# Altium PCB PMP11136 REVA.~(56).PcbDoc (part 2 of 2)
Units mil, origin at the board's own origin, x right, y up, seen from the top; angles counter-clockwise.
Board outline 4320 x 3450 mil, 4 copper layers (Top Layer, Signal Layer 1, Signal Layer 2, Bottom Layer), stack 79.834 mil thick; 234 components, 94 nets, 538 pads, 218 vias.
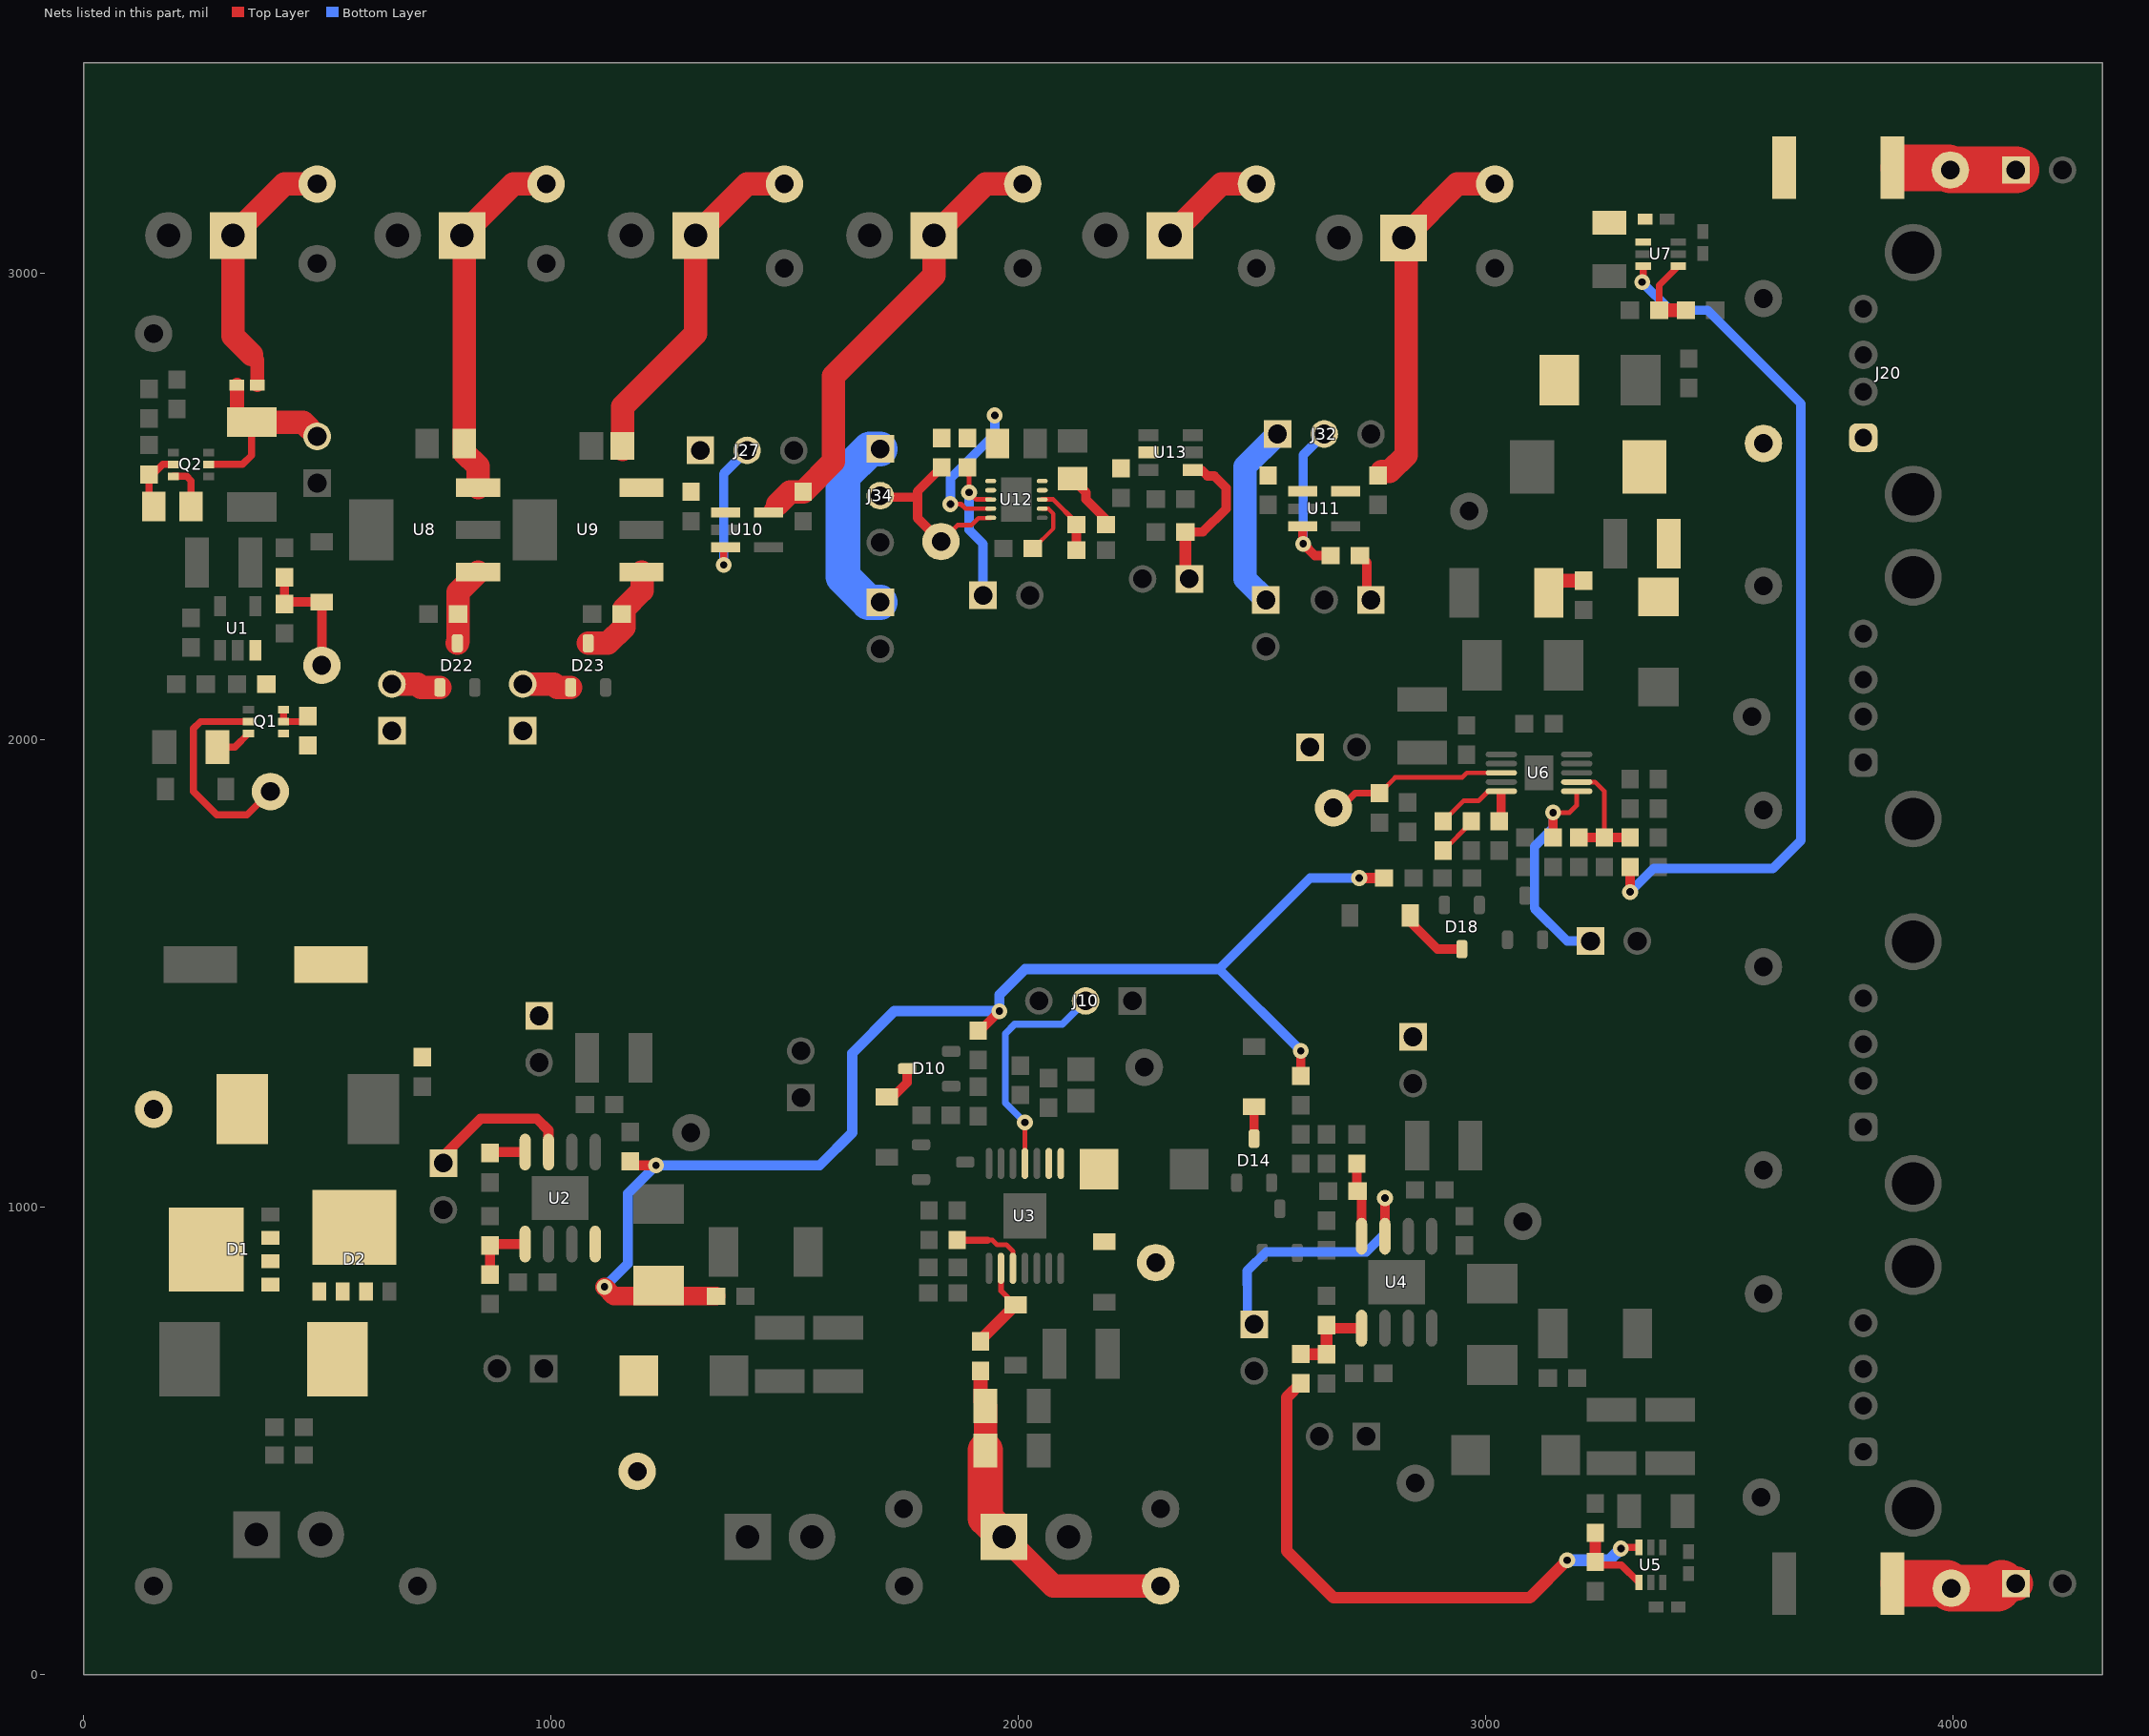
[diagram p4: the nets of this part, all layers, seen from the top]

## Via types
v1: diameter 34, hole 16, Top Layer to Bottom Layer, 193 vias
v2: diameter 19.68, hole 7.87, Top Layer to Bottom Layer, tented top, 12 vias
v3: diameter 18, hole 8, Top Layer to Bottom Layer, 5 vias
v4: diameter 15.75, hole 7.87, Top Layer to Bottom Layer, 4 vias
v5: diameter 19.68, hole 7.87, Top Layer to Bottom Layer, 4 vias

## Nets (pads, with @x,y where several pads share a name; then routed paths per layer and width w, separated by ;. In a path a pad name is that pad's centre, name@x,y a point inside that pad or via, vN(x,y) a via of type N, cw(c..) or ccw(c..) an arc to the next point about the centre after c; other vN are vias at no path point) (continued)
NetC39_2: C39.2 R45.2 | length 85.4
  Top Layer w30: R45.2@3135.55,2315 3162.05,2341.5 C39.2@3210,2341.5
NetC40_1: C40.1 TP25.1 U6.3 | length 390.4
  Top Layer w10: C40.1@2773.23,1886.5 2806.73,1920 2950,1920 2960,1930 U6.3@3033.98,1930
  Top Layer w15: TP25.1@2674.68,1855 2690,1855 2721.5,1886.5 C40.1@2773.23,1886.5
NetC41_1: C41.1 R39.2 | length 87.8
  Top Layer w10: R39.2@2909.68,1763.5 2969.68,1823.5 C41.1@2969.68,1826.5
NetC43_1: C43.1 C44.1 D17.2 L5.2
NetC45_1: C45.1 J20.1 R35.1 R37.2 TP42.1 U7.4
NetC47_1: C47.1 J23.1 TP30.1 U8.3 | length 779.2
  Top Layer w50: U8.3@844.17,2540.55 844.17,2585.83 815,2615 C47.1@815,2635 815,3075 J23.1@810,3080 920,3190 TP30.1@990,3190
NetC48_1: C48.1 D22.3 U8.1 | length 170.5
  Top Layer w50: D22.3@800,2207.24 800.39,2207.64 800.39,2210.39 801.5,2211.5 C48.1@801.5,2270 801.5,2316.77 U8.1@844.17,2359.45
NetC49_1: C49.1 C51.1 J24.1 J27.1 TP32.1 U9.3 U10.1 | length 758.2
  Top Layer w50: C49.1@1153.46,2622.17 C49.1@1153.46,2630 1153.46,2713.46 1310,2870 J24.1@1310,3080 1420,3190 TP32.1@1500,3190
NetC50_1: C50.1 D23.3 U9.1 | length 224.9
  Top Layer w50: D23.3@1080,2207.24 1122.24,2207.24 1156.46,2241.46 1156.46,2281.46 1195,2320 1195,2358.62 U9.1@1194.17,2359.45
NetC52_1: C52.1 J26.1 TP34.1 U10.5 | length 997.3
  Top Layer w20: U10.5@1466,2487.4 1466,2496 1475,2505
  Top Layer w30: 1475,2505 1485,2505
  Top Layer w50: 1485,2505 1511.5,2531.5 C52.1@1540,2531.5 1605,2596.5 1605,2779 1820,2994 J26.1@1820,3080 1930,3190 TP34.1@2010,3190
NetC53_1: C53.1 J28.1 J34.1 R49.2 R50.2 U12.1 U12.2 U12.4 | length 741.4
  Top Layer w10: v1(1855,2505) 1877.75,2505 1887.44,2495.32 U12.4@1941.18,2495.32
  Bottom Layer w20: v1(1855,2505) 1855,2560 1950,2655 v1(1950,2695)
  Bottom Layer w75: J28.1@1705,2295 1680,2295 1625,2350 1625,2565 1683.02,2623.02 J34.1@1705,2623.02
NetC54_1: C54.1 J31.1 TP37.1 U11.5 | length 787.7
  Top Layer w25: C54.1@2770,2566.5 C54.1@2778.5,2575
  Top Layer w50: C54.1@2778.5,2575 2795,2575 2830,2610 2830,3070 J31.1@2825,3075 2940,3190 TP37.1@3020,3190
NetC55_1: C55.1 J29.1 J32.1 U11.1 | length 402.6
  Bottom Layer w50: J29.1@2530,2300 2485,2345 2485,2585 J32.1@2555,2655
NetC56_1: C56.1 C59.1 J33.1 R51.2 TP36.1 U12.9 U12.10 U13.5 | length 358.9
  Top Layer w20: C56.1@2116.3,2560 2116.3,2558.7 2145,2530 2145,2515 2187.8,2472.2 R51.2@2187.8,2461.3
  Top Layer w50: J33.1@2325,3080 2435,3190 TP36.1@2510,3190
NetC57_1: C57.1 U12.7 | length 122
  Top Layer w9: C57.1@2031.5,2410 2032.48,2410 2075.6,2453.12 2075.6,2484.4 2064.68,2495.32 U12.7@2051.42,2495.32
NetD1_1: D1.1 D1.2 D1.3 D2.1 D2.2 D2.3 L1.2
NetD4_1: D4.1 J3.1 TP4.1 | length 567
  Top Layer w30: 360,2825 371.65,2813.35 D4.1@371.65,2760
  Top Layer w50: 360,2825 320,2865 J3.1@320,3080 430,3190 TP4.1@500,3190
NetD4_2: D4.2 J2.2 Q2.5 R1.2 | length 416.5
  Top Layer w15: Q2.5@267.4,2590 340,2590 360,2610 R1.2@360,2680.24
  Top Layer w20: 328.35,2711.89 R1.2@360,2680.24
  Top Layer w30: 328.35,2711.89 D4.2@328.35,2760
  Top Layer w50: R1.2@360,2680.24 360.24,2680 470,2680 J2.2@500,2650
NetD5_1: D5.1 R3.1 R7.1 TP7.1 | length 274.2
  Top Layer w20: R7.1@430,2348.5 R3.1@430,2291.5 434.04,2295.53 D5.1@510,2295.53 TP7.1@510,2160
NetD7_2: D7.2 L3.2 TP11.1 U3.1 U3.2
NetD8_2: D8.2 R11.2 U3.9 | length 200.8
  Top Layer w12: U3.9@1963.31,869.7 1963.31,821.69 1993.62,791.38 D8.2@1994.49,791.38
  Top Layer w25: R11.2@1919.49,713.41 1919.49,716.38 D8.2@1994.49,791.38
NetD10_3: D10.3 D12.1 | length 85.3
  Top Layer w20: D12.1@1719.49,1236.38 1731.46,1236.38 1762.24,1267.17 D10.3@1762.24,1296.91
NetD14_3: D14.3 D15.1 | length 68.3
  Top Layer w20: D14.3@2505,1147.24 D15.1@2505,1215.53
NetD18_3: D18.3 D20.1 | length 148.7
  Top Layer w20: D20.1@2839.15,1625 2839.15,1610.85 2897.24,1552.76 D18.3@2949.68,1552.76
NetD22_1: D22.1 J22.2 | length 105.6
  Top Layer w50: J22.2@660,2120 715,2120 722.24,2112.76 D22.1@762.6,2112.76
NetD23_1: D23.1 J25.2 | length 105.6
  Top Layer w50: J25.2@940,2120 1006.61,2120 1013.86,2112.76 D23.1@1042.6,2112.76
NetJ5_1: J5.1 U2.3 | length 330.1
  Top Layer w22: J5.1@770,1095 770,1110 850,1190 970,1190 995,1165 U2.3@995,1118.43
NetJ7_1: J7.1 R11.1 R17.2 R18.2 TP14.1 | length 754.8
  Top Layer w30: R11.1@1919.49,650.41 1919.49,585.51 R18.2@1930,575
  Top Layer w50: R17.2@1930,480 R18.2@1930,575 ; J7.1@1970,295 2075,190 TP14.1@2305,190
  Top Layer w75: R17.2@1930,480 1930,335 J7.1@1970,295
NetJ10_2: J10.2 U3.4 | length 495.9
  Top Layer w10: U3.4@2014.49,1094.11 v1(2014.49,1181.91)
  Bottom Layer w15: v1(2014.49,1181.91) 1972.63,1223.77 1972.63,1371.73 1992.81,1391.91 2094.49,1391.91 J10.2@2144.49,1441.91
NetJ12_1: J12.1 R22.2 TP17.1 | length 272.1
  Top Layer w50: R22.2@3871.14,195 R22.2@3895,195
  Top Layer w75: 4105,195 J12.1@4135,195
  Top Layer w100: R22.2@3895,195 3986.97,195 TP17.1@3996.97,185 4095,185 4105,195
NetJ13_1: J13.1 U4.3 | length 605.4
  Top Layer w20: U4.3@2785,938.43 v1(2785,1020)
  Bottom Layer w20: J13.1@2505,750 2490.68,764.32 2490.68,834.45 2490.13,835 2490.13,864.45 2530.68,905 2745,905 2785,945 v1(2785,1020)
NetJ18_1: J18.1 R36.2 U6.6 | length 511.3
  Top Layer w10: v1(3144.68,1845) 3180,1845 3195,1860 3195,1875 3195.39,1875.39 U6.6@3195.39,1890.63
  Top Layer w20: R36.2@3144.68,1791.5 v1(3144.68,1845)
  Bottom Layer w20: v1(3144.68,1845) 3144.68,1811.99 3105,1772.3 3105,1640 3175,1570 J18.1@3225,1570
NetJ19_1: J19.1 R35.2 TP23.1 | length 265.9
  Top Layer w50: R35.2@3871.14,3225 R35.2@3895,3225
  Top Layer w100: R35.2@3895,3225 3990,3225 TP23.1@3995,3220 J19.1@4135,3220
NetJ27_2: J27.2 U10.3 | length 305
  Top Layer w15: v1(1370,2375) 1370,2408.6 U10.3@1374,2412.6
  Bottom Layer w20: v1(1370,2375) 1370,2570 J27.2@1420,2620
NetJ30_1: J30.1 R49.1 U12.3 | length 339.9
  Top Layer w10: R49.1@1891.3,2583.5 1891.3,2568.7 1895,2565 v1(1895,2530) 1910,2515 U12.3@1941.18,2515
  Bottom Layer w20: v1(1895,2530) 1895,2450 1925,2420 J30.1@1925,2310
NetJ32_2: J32.2 R53.2 U11.3 | length 360.5
  Top Layer w20: U11.3@2609,2457.6 2609,2421 v1(2610,2420) 2635,2395 R53.2@2668.5,2395
  Bottom Layer w20: v1(2610,2420) 2610,2610 J32.2@2655,2655
NetJ34_2: J34.2 R50.1 TP40.1 U12.5 | length 408.9
  Top Layer w10: TP40.1@1835,2425 1870,2460 1900,2460 1915,2475 1940.55,2475 U12.5@1941.18,2475.63
  Top Layer w20: J34.2@1705,2523.02 1708.02,2520 1785,2520 ; TP40.1@1835,2425 1785,2475 1785,2520 ; R50.1@1836.3,2583.5 1785,2532.2 1785,2520
NetJ35_1: J35.1 R53.1 | length 104.7
  Top Layer w20: R53.1@2731.5,2395 2746.5,2380 2746.5,2308.5 J35.1@2755,2300
NetJ36_1: J36.1 R54.1 U13.1 | length 343.9
  Top Layer w20: R54.1@2357.8,2445.47 2395.47,2445.47 2445,2495 2445,2540 2420,2565 2405,2565 2391.93,2578.07 U13.1@2373.54,2578.07
  Top Layer w25: R54.1@2357.8,2445.47 2357.8,2353.5 J36.1@2366.3,2345
NetQ1_2: Q1.2 TP8.1 | length 465.2
  Top Layer w15: Q1.2@352.95,2039.77 250.23,2039.77 235,2024.54 235,1890 285,1840 350,1840 TP8.1@400,1890
NetQ1_3: Q1.3 R6.1 | length 77.9
  Top Layer w15: R6.1@287.09,1985 323.77,1985 Q1.3@352.95,2014.18
NetQ1_5: Q1.5 Q1.6 R2.1 | length 82.7
  Top Layer w15: Q1.6@427.75,2065.36 Q1.5@427.75,2039.77 468.27,2039.77 R2.1@480,2051.5
NetQ2_2: Q2.2 R5.1 R8.2 | length 134.1
  Top Layer w15: R5.1@150,2500 140,2510 R8.2@140,2568.5 148.5,2568.5 170,2590 Q2.2@192.6,2590
NetQ2_3: Q2.3 R5.2 | length 96.3
  Top Layer w15: Q2.3@192.6,2564.41 220.59,2564.41 230,2555 R5.2@230,2500
NetR10_1: R10.1 R14.2 U2.5 | length 138.3
  Top Layer w22: R10.1@870,856.5 R14.2@870,918.5 873.07,921.57 U2.5@945,921.57
NetR15_2: R15.2 U2.4 | length 75.8
  Top Layer w22: R15.2@870,1116.5 871.93,1118.43 U2.4@945,1118.43
NetR16_2: R16.2 U3.10 | length 165.9
  Top Layer w10: 1935,930 1945,930 1955,920 1975,920 1988.9,906.1 U3.10@1988.9,869.7
  Top Layer w15: R16.2@1869.49,930.41 1869.9,930 1935,930
NetR24_1: R24.1 R26.2 U4.4 | length 159.2
  Top Layer w20: R24.1@2725,1093.5 2725,1036.5 R26.2@2726.5,1035 2735,1026.5 U4.4@2735,938.43
NetR25_2: R25.2 R32.1 U5.1 | length 173.6
  Top Layer w15: R32.1@3235,241.5 3241.5,235 3291.02,235 U5.1@3328.42,197.6
  Top Layer w25: R32.1@3235,241.5 R25.2@3235,303.5
NetR27_1: R27.1 R31.2 R33.2 U4.5 | length 194.9
  Top Layer w22: R31.2@2660,747.95 2666.38,741.57 U4.5@2735,741.57
  Top Layer w25: R33.2@2605,686.5 2605.55,685.94 R27.1@2660,685.94 R31.2@2660,747.95
NetR33_1: R33.1 U5.6 | length 1210.3
  Top Layer w15: v1(3290,270) 3292.4,272.4 U5.6@3328.42,272.4
  Top Layer w25: R33.1@2605,623.5 2575,593.5 2575,565 2575,265 2675,165 3095,165 v1(3175,245)
  Bottom Layer w25: v1(3175,245) 3265,245 v1(3290,270)
NetR39_1: R39.1 R42.2 U6.5 | length 216.8
  Top Layer w10: R39.1@2909.68,1826.5 2953.19,1870 2985,1870 3005.63,1890.63 U6.5@3033.98,1890.63 U6.5@3033.98,1886.71
  Top Layer w15: U6.5@3033.43,1886.16 U6.5@3033.98,1886.71
  Top Layer w20: R42.2@3029.68,1826.5 3033.43,1830.24 U6.5@3033.43,1886.16
NetR40_1: R40.1 R44.2 R48.2 U6.7 | length 276.4
  Top Layer w10: U6.7@3195.39,1910.32 3234.68,1910.32 3254.68,1890.32 R40.1@3254.68,1791.5
  Top Layer w20: R44.2@3199.68,1791.5 R40.1@3254.68,1791.5 R48.2@3309.68,1791.5
NetR41_2: R41.2 R46.1 U7.1 | length 168.4
  Top Layer w15: R41.2@3371.83,2920 3371.83,2973.52 U7.1@3412.72,3014.41
  Top Layer w30: R41.2@3371.83,2920 R46.1@3428.84,2920
NetR48_1: R48.1 U7.6 | length 1882.2
  Top Layer w15: v1(3335.31,2980) 3337.91,2982.6 U7.6@3337.91,3014.41
  Top Layer w20: v1(3309.68,1675) R48.1@3309.68,1728.5
  Bottom Layer w20: v1(3309.68,1675) 3360,1725.32 3615.31,1725.32 3675,1785 3675,2720 3475,2920 3395.31,2920 v1(3335.31,2980)
NetR51_1: R51.1 R52.2 U12.8 | length 152.9
  Top Layer w10: U12.8@2051.42,2515 2075,2515 2124.8,2465.2 R51.1@2124.8,2461.3
  Top Layer w20: R52.2@2124.8,2406.3 R51.1@2124.8,2461.3
SYNC: C11.2 C15.1 D9.1 L2.1 R20.1 R28.1 R38.1 TP9.1 U2.8 | length 2907.6
  Top Layer w20: R20.1@1914.49,1378.41 1918.41,1378.41 v1(1960,1420) ; R28.1@2605,1281.5 v1(2605,1335)
  Top Layer w22: C11.2@1170,1098.5 1178.5,1090 v1(1225,1090) ; v1(2730,1705) R38.1@2783.19,1705
  Top Layer w40: v1(1115,830) 1135,810 C15.1@1353.5,810
  Bottom Layer w20: v1(2605,1335) 2430,1510 2625,1705 v1(2730,1705)
  Bottom Layer w22: v1(1115,830) 1165,880 1165,1030 v1(1225,1090) 1575,1090 1645,1160 1645,1330 1735,1420 v1(1960,1420) 1960,1455 2015,1510 2430,1510
VIN_FLTR: C3.1 C4.1 C6.1 D1.5 D2.5 D3.1 J4.1 J11.1 J17.1 J22.1 J25.1 Q1.4 R2.2 TP2.1 U1.3
pads on no net: D1.4 D2.4 D10.2 D11.2 D14.2 D16.2 D18.2 D21.2 D22.2 D23.2 J14.2 J14.3 J15.2 J15.3 J20.2 J20.3 J21.2 J21.3 U10.4 U11.4 U13.3 U13.4

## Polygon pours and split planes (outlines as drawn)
GND on Top Layer "Top Layer-No Net 32" (solid, remove dead copper, pour order 98): 0,0 0,3450 4320,3450 4320,0
NetC45_1 on Top Layer "Top Layer-No Net 31" (solid, remove dead copper, pour order 90): 3765,2953.86 3765,2695 3785,2675 3830,2675 3835,2675 3835,2625 3835,2624.76 3825.24,2615 3730,2615 3590,2615 3575,2630 3575,2695 3575,2855 3590,2870 3615,2870 3640,2870 3660,2890 3660,2915 3660,2930 3685,2955
NetC45_1 on Top Layer "Top Layer-No Net 30" (solid, remove dead copper, pour order 86): 3352.28,3061.18 3321.18,3061.18 3320,3060 3297.77,3082.23 3286.06,3082.23 3177.77,3082.23 3165,3095 3165,3225 3165,3290 3195,3320 3680,3320 3760,3320 3795,3285 3800,3280 3800,3125 3800,2988.86 3781.14,2970 3765,2953.86 3765,2915 3660,2915 3660,2950 3660,2970 3625,3005 3620,3010 3590,3010 3575,3010 3545,3040 3545,3115 3545,3135 3525,3155 3520,3160 3388.19,3160 3355,3126.81 3352.28,3124.1 3352.28,3065 3352.28,3062.64 3350.83,3061.18 3349.65,3060 3320,3060
NetC36_1 on Top Layer "Top Layer-No Net 29" (solid, remove dead copper, pour order 84): 3395,2830 3395,2840.5 3395,2845 3375,2865 3360,2880 3350,2880 3330,2900 3330,2938.7 3330,2940 3305,2965 3300.75,2969.25 3300.75,3020 3180,3020 3170,3010 3170,2930 3170,2880 3180,2870 3185,2865 3240,2865 3250,2865 3275,2840 3275,2720 3285,2710 3395,2710
NetC36_1 on Top Layer "Top Layer-No Net 27" (solid, remove dead copper, pour order 82): 3295,2850 3280,2835 3280,2715 3285,2710 3295,2700 3384.76,2700 3395,2700 3415,2680 3425,2670 3425,2645 3425,2560 3435,2550 3515,2470 3570,2415 3600,2385 3625,2385 3650,2360 3650,2305 3650,2300 3625,2275 3610,2260 3610,2165 3650,2125 3665,2110 3665,2010 3665,1980 3625,1940 3555,1870 3555,1855 3555,1780 3565,1770 3805,1770 3825,1790 3830,1795 3830,1850 3830,1860 3850,1880 3850,1975 3850,1977.05 3837.05,1990 3832.05,1995 3781.14,1995 3775,1995 3760,2010 3760,2115 3760,2253.86 3781.14,2275 3800,2293.86 3800,2345 3800,2415 3655,2560 3630,2560 3590,2560 3545,2605 3546,2606 3546,2684.24 3546,2769 3535,2780 3453.7,2780 3405,2780 3395,2790 3395,2830 3395,2840.5 3387,2848.5
NetC43_1 on Top Layer "Top Layer-No Net 28" (solid, remove dead copper, pour order 80): 3315.5,2354.85 3249.85,2354.85 3245,2350 3245,2255 3280,2220 3490,2220 3500,2230 3500,2460 3445,2515 3405,2555 3405,2660 3405,2661.18 3384.76,2681.42 3283.58,2681.42 3255,2710 3255,2833.5 3238.5,2850 3075,2850 3060,2835 3060,2693.58 3083.58,2670 3165,2670 3215,2620 3215,2540 3269.85,2485.15 3315.5,2485.15
NetC34_2 on Top Layer "Top Layer-No Net 26" (solid, remove dead copper, pour order 76): 3125,2016.3 3149.13,2016.3 3149.57,2016.3 3165,2000.87 3165,1965 3225,1965 3245,1985 3560,1985 3605,2030 3605,2065 3605,2070 3580,2095 3500,2175 3500,2195 3490,2205 3330,2205 3275.01,2205 3231.04,2248.98 3230,2248.98 3230,2265 3225,2270 3215,2270 3195,2270 3190,2265 3189,2264 3189,2249.02 3098.16,2249.02 3080,2230.86 3075,2225.86 3075,2120 3075,2100 3095,2080 3100,2075 3115,2075 3125,2065
NetC32_2 on Top Layer "Top Layer-No Net 25" (solid, remove dead copper, pour order 74): 2680,2015 2680,2020 2710,2050 2710.32,2049.68 2864.68,2049.68 2885.32,2049.68 2910,2025 2950,1985 2955.55,1985 2975,1965.55 2980.55,1960 2988.23,1960 3039.64,1960 3045.38,1954.26 3045.38,1945.26 3011.26,1945.26 3045.38,1945.26 3016.26,1945.26 3012,1941 2996,1941 2982,1941 2967,1941 2947.02,1941 2945,1938.98 2941.02,1935 2860,1935 2700,1935 2680,1955
NetC28_1 on Top Layer "Top Layer-No Net 24" (solid, remove dead copper, pour order 72): 3405,385.43 3405,323.98 3379.6,298.57 3375.19,294.17 3375.19,268.33 3428.48,268.33 3446.81,250 3475,250 3485,240 3485,160 3485,155 3515,125 3670,125 3785,125 3820,160 3825,165 3825,325 3825,380 3840,395 3840,440 3840,500 3830,510 3705,510 3680,510 3640,470 3599.24,429.24 3590.02,429.24 3569.24,429.24 3565,425 3525,385
NetC25_1 on Top Layer "Top Layer-No Net 23" (solid, remove dead copper, pour order 70): 3410,520 3460,520 3470,530 3475,535 3475,645 3450,670 3385,735 3385,880 3385,1055 3455,1125 3535,1205 3845,1205 3845,1095 3825,1075 3765,1015 3700,1015 3605,1015 3555,965 3540,950 3540,810 3540,780 3570,750 3635,685 3635,585 3635,490 3610,465 3590,445 3580,445 3565,445 3525,405 3520,405 3410,405
NetC25_1 on Top Layer "Top Layer-No Net 22" (solid, remove dead copper, pour order 68): 3205,595 3120,595 3085,560 3085,470 3085,325 3105,305 3185,305 3200,320 3200,335 3201.3,335 3211.3,345 3225,345 3253.7,345 3284.13,314.57 3335,314.57 3335,385 3355,405 3385,405 3445.51,405 3457.99,417.48 3457.99,520 3215,520 3210,525 3205,530 3205,540
NetC24_2 on Top Layer "Top Layer-No Net 21" (solid, remove dead copper, pour order 66): 2870,780 3090,780 3090,675 3120,645 3120,615 3090,585 3070,565 3070,335 3070,325 3050,305 2830,305 2810,325 2810,440 2870,500
NetC22_2 on Top Layer "Top Layer-No Net 20" (solid, remove dead copper, pour order 64): 2820,905 2850,905 2850,970 2870,990 2880,1000 2881,1001 2881,1056.22 2881,1070.37 2890,1079.37 2900,1079.37 2914.37,1079.37 2925,1090 2925,1160 2925,1280 2905,1300 2805,1300 2800,1300 2780,1280 2770,1270 2770,1110 2770,1085 2815,1040 2815,975 2815,910 2820,905
NetC14_1 on Top Layer "Top Layer-No Net 19" (solid, remove dead copper, pour order 60): 2150,815 2130,795 2130,770 2130,400 2100,370 2055,325 2055,310 2055,270 2065,260 2080,245 2140,245 2240,245 2250,255 2260,265 2285,265 2335,265 2355,285 2355,495 2355,790 2330,815
NetD7_2 on Top Layer "Top Layer-No Net 18" (solid, remove dead copper, pour order 58): 2060,1125 2060,1055 2080,1035 2080,935 2100,915 2120,895 2120,865 2130,855 2150,835 2320,835 2345,860 2343.72,861.28 2343.72,930.91 2270.91,930.91 2270,930 2269.49,930.51 2269.49,1002.79 2269.49,1149.49 2270,1150 2269.49,1150.51 2269.49,1161.03 2268.97,1161.03 2260,1170 2145,1170 2125,1150 2112.42,1137.42 2105,1137.42 2072.42,1137.42 2060,1125
NetC12_1 on Top Layer "Top Layer-No Net 17" (solid, remove dead copper, pour order 43): 1505,1305 1485,1325 1485,1495 1495,1505 1500,1510 1760,1510 1845,1595 1860,1610 2300,1610 2360,1610 2425,1545 2425,1390 2425,970 2410,955 2290,955 2290,1161.88 2267.13,1184.76 2266.88,1185 2175,1185 2140,1185 2125,1170 2105,1150 2100,1150 2075,1150 2050,1125 2050,1115 2050,1068.52 2030,1068.52 2030,1160 2035,1165 2040,1170 2040,1195 2040,1228.7 2046.3,1235 2051.3,1240 2083.7,1240 2085,1240 2100,1255 2163.03,1255 2190,1255 2221,1286 2221,1349.24 2221,1364 2205,1380 2195,1390 2195,1445 2195,1460 2180,1475 2170,1485 2145,1485 1965,1485 1935,1455 1915,1435 1895,1435 1885,1435 1855,1405 1830,1380 1735,1380 1730,1380 1655,1305
3.3V_SW on Top Layer "Top Layer-No Net 16" (solid, remove dead copper, pour order 56): 1370,250 1370,435 1375,440 1435,500 1435,530 1435,575 1440,580 1445,585 1770,585 1770,495 1755,480 1650,375 1627.8,375 1540,375 1485,320 1485,250
3.3V_SW on Top Layer "Top Layer-No Net 14" (solid, remove dead copper, pour order 54): 1320,755 1320,517.95 1732.95,517.95 1770,555 1770,670 1770,935 1735,970 1715,990 1715,1030 1715,1035 1660,1090 1645,1105 1645,1255 1645,1260 1635,1270 1505,1270 1500,1270 1485,1255 1485,1070 1485,1045 1540,990 1550,980 1590,980 1605,965 1605,865 1605,855 1625,835 1630,830 1670,830 1675,830 1690,815 1690,750 1690,715 1680,705 1670,695 1510,695 1430,695 1420,705 1420,755
SYNC on Top Layer "Top Layer-No Net 15" (solid, remove dead copper, pour order 52): 1085,950 1085,560 1125,520 1155,490 1155,435 1220,435 1220,490 1245,515 1247.95,517.95 1285,517.95 1285,940 1275,950 1125,950
NetC9_2 on Top Layer "Top Layer-No Net 13" (solid, remove dead copper, pour order 50): 1050,1375 1045,1375 1025,1355 1015,1345 980,1345 950,1345 940,1335 925,1320 925,1265 935,1255 950,1255 1005,1255 1015,1245 1030,1230 1030,1170 1030,1090 1035,1085 1060,1085 1065,1090 1065,1145 1065,1150 1080,1165 1090,1175 1090,1201.3 1090,1235 1105,1250 1105,1375
VIN_FLTR on Top Layer "Top Layer-No Net 12" (solid, remove dead copper, pour order 46): 910,2050 2085,2050 2620,2050 2655,2015 2655,1955 2655,1925 2615,1885 2615,1695 2615,1645 2740,1520 2865,1395 2875,1395 2875,1335 2755,1335 2690,1335 2655,1370 2610,1415 2520,1415 2450,1415 2350,1515 2345,1520 1220,1520 1145,1520 1005,1380 910,1380
3.3V_SW on Top Layer "Top Layer-No Net 11" (solid, remove dead copper, pour order 39): 2575,2245 2575,2150 2560,2135 2295,2135 1725,2135 1670,2135 1640,2165 1640,2220 1660,2240 2195,2240 2555,2240 2575,2220
NetC54_1 on Top Layer "Top Layer-No Net 10" (solid, remove dead copper, pour order 37): 2670,2520 2670,2590 2690,2610 2770,2610 2820,2610 2820,2545 2751.3,2545 2726.3,2520 2725,2520
NetC55_1 on Top Layer "Top Layer-No Net 9" (solid, remove dead copper, pour order 35): 2640,2520 2640,2580 2640,2592 2591,2641 2585,2647 2585,2685 2525,2685 2515,2675 2515,2670 2515,2546.3 2516.3,2545 2553.7,2545 2553.7,2544.84 2563.54,2535 2578.54,2520 2585,2520
NetC56_1 on Top Layer "Top Layer-No Net 8" (solid, remove dead copper, pour order 33): 2040,2590 2040,2530 2160,2530 2180,2550 2238.7,2550 2240,2551.3 2240,2595 2240.4,2595 2245.4,2600 2248.27,2602.87 2302.87,2602.87 2306.61,2606.61 2306.61,2623.39 2301.92,2628.08 2245.4,2628.08 2245.4,2668.1 2245,2668.5 2271.5,2695 2280,2695 2330,2695 2375,2740 2375,3130 2275,3130 2255,3110 2255,3035 2220,3000 2185,3000 2135,2950 2135,2693.3 2159.8,2668.5 2159.8,2603 2073.43,2603 2073.3,2602.87
NetC56_1 on Top Layer "Top Layer-No Net 7" (solid, remove dead copper, pour order 29): 2040,2585 2040,2530 2160,2530 2165,2535 2185,2555 2230,2600 2260,2600 2300,2600 2306.61,2606.61 2306.61,2615.47 2306.61,2623.39 2305,2625 2300,2630 2290,2630 2251.34,2630 2244.84,2636.5 2245,2636.65 2245,2670 2340,2765 2375,2800 2375,3030 2375,3130 2275,3130 2255,3110 2255,3035 2230,3010 2220,3000 2170,3000 2135,2965 2135,2760 2185,2710 2185,2685 2170,2670 2161.3,2670 2156.3,2665 2156.3,2620 2156.3,2606.3 2155,2605 2076.3,2605 2075,2605 2065,2595 2060,2590 2040,2590
NetC53_1 on Top Layer "Top Layer-No Net 6" (solid, remove dead copper, pour order 27): 1675,2590 1755,2590 1790,2625 1895,2625 1909.84,2625 1919.84,2615 1922.3,2612.54 1922.3,2605 1922.3,2532.7 1925,2530 1945,2530 1950,2530 1950,2531.09 1957.25,2538.34 1960,2541.09 1960,2575 1980,2595 1980,2606.46 1980,2750 1965,2765 1805,2765 1690,2765 1675,2750
NetC49_1 on Top Layer "Top Layer-No Net 5" (solid, remove dead copper, pour order 25): 1318.7,2515 1155,2515 1130,2540 1130,2650 1345,2650 1350,2645 1350,2620 1350,2590 1375,2565 1385.48,2554.52 1385.48,2477.42 1342.58,2477.42 1305,2515
VIN_FLTR on Top Layer "Top Layer-No Net 4" (solid, remove dead copper, pour order 23): 498.7,2010 431.93,2010 427.75,2014.18 426.93,2015 405,2015 400,2020 400,2110 400,2182.76 375.95,2206.82 355,2185.87 355,2160.94 355,2153.39 370,2138.39 375,2133.39 375,1990 375,1985 390,1970 495,1970
VIN_FLTR on Top Layer "Top Layer-No Net 3" (solid, remove dead copper, pour order 21): 1005,1675 1005,2035 990,2050 620,2050 560,2050 515,2005 461.3,2005 461.3,1861.3 430,1830 350,1750 350,1675
VIN_FLTR on Top Layer "Top Layer-No Net 2" (solid, remove dead copper, pour order 19): 690,875 490,875 490,875.12 470.75,894.37 470,895.12 470,960 470,985 455,1000 355,1000 330,975 330,860 330,855 340,845 340,795 340,785 330,775 130,775 0,775 0,1420 325,1420 345,1440 350,1445 350,1580 350,1595 350,1700 990,1700 1000,1690 1005,1685 1005,1600 1005,1380 845,1380 823.7,1380 743.7,1300 738.7,1305 630,1305 555,1305 545,1295 545,1225 545,1130 560,1115 625,1115 625,1100 650,1075 670,1075 680,1075 690,1065 690,900
NetD1_1 on Top Layer "Top Layer-No Net 1" (solid, remove dead copper, pour order 17): 360,950 360,785 360,775 340,755 330,745 330,740 330,610 340,600 345,595 620,595 620,855 495,855 470,855 450,875 450,930 450,950
NetC1_1 on Top Layer "Top Layer-No Net" (solid, remove dead copper, pour order 15): 0,0 430,0 430,565 415,580 350,580 340,580 315,605 315,755 0,755
GND on Bottom Layer "Bottom Layer-No Net 1" (solid, remove dead copper, pour order 96): 0,0 0,3450 4320,3450 4320,0
3.3V_SW on Bottom Layer "Bottom Layer-No Net" (solid, remove dead copper, pour order 62): 1565,1205 1440,1205 1370,1205 1325,1250 1325,1365 1325,2055 1495,2225 1705,2225 1715,2225 1735,2205 1735,2115 1710,2090 1680,2060 1580,2060 1550,2060 1490,2000 1490,1885 1490,1310 1510,1290 1530,1290 1560,1290 1565,1285
GND on Signal Layer 2 "Signal Layer 2-No Net" (solid, remove dead copper, pour order 92): 0,-5 0,3450 4320,3450 4325,3445 4325,0
GND on Signal Layer 1 "Signal Layer 1-No Net" (solid, remove dead copper, pour order 94): 0,5 0,3450 4320,3450 4320,0

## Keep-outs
Keep-Out Layer:
  the board outline again, w7
  text ".Layer_Name" at 577,-858.49 h60

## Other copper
Top Layer:
  text ".Layer_Name" at 577,-858.49 h60
Bottom Layer:
  text ".Layer_Name" at 577,-858.49 h60

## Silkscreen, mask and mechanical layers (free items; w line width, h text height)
Top Overlay:
  text "Mic" at 875,3385 h40 r180
  text "STBY" at 1400,3385 h40 r180
  text "Gnd" at 215,3380 h40 r180
  text "Ant" at 395,3380 h40 r180
  text "Gnd" at 705,3380 h40 r180
  text "Gnd" at 1205,3380 h40 r180
  text "Gnd" at 1710,3380 h40 r180
  text "STBY" at 1905,3380 h40 r180
  text "Gnd" at 2220,3380 h40 r180
  text "1.2V" at 2405,3380 h40 r180
  text "Gnd" at 2720,3380 h40 r180
  text "1.8V" at 2900,3380 h40 r180
  text "12V" at 395,3320 h40 r180
  text "3.3V" at 885,3320 h40 r180
  text "5V" at 1370,3320 h40 r180
  text "3.3V" at 1900,3315 h40 r180
  text ".PRJ_Number" at 1310,1770 h60
  text ".PCB_Rev" at 1910,1770 h60
  text "Vin" at 295,75 h40
  text "Gnd" at 480,75 h40
  text "3.3VSW" at 1280,60 h40
  text "Gnd" at 1545,60 h40
  text "C" at 1945,60 h40
  text "A" at 2115,60 h40
  text ".Layer_Name" at 577,-858.49 h60
Bottom Overlay:
  text ".Layer_Name" at 577,-858.49 h60
Top Paste:
  text ".Layer_Name" at 577,-858.49 h60
Bottom Paste:
  text ".Layer_Name" at 577,-858.49 h60
Top Solder:
  text ".Layer_Name" at 577,-858.49 h60
  text ".Layer_Name" at 577,-858.49 h60
Bottom Solder:
  text ".Layer_Name" at 577,-858.49 h60
Drill Guide:
  text ".Layer_Name" at 577,-858.49 h60
M1 Board Outline:
  lines w7: 0,0 4320,0 4320,3450 0,3450 0,0
  lines w10: 0,0 4320,0 4320,3450 0,3450 0,0
  text ".Layer_Name" at 577,-858.49 h60
M2 Board Dimensions:
  rectangle: 125,-400 500,-275
  rectangle: 0,-275 125,-150
  lines w7: 0,-275 1000,-275 ; 125,-400 125,-150 ; 250,-400 250,-150 ; 500,-400 500,-150 ; 750,-400 750,-150 ; 0,-400 0,-150 1000,-150 1000,-400 0,-400
  text ".Layer_Name" at 577,-858.49 h60
M3 3D STEP Top:
  text ".Layer_Name" at 577,-858.49 h60
M4 3D STEP Bottom:
  text ".Layer_Name" at 577,-858.49 h60
M5 Assembly Top:
  lines w10: -292,-930.17 6308,-930.17 ; -292,-726.83 6310,-726.83 ; -292,-523.5 -292,-1133.5 3713,-1133.5 6310,-1133.5 6310,-523.5 -291.5,-523.5 -291.5,-1133.5 1284,-1133.5 ; 2173,-1133.5 2173,-523.5 ; 3440,-726.83 3440,-523.5 ; 4280,-726.83 4280,-523.5 ; 4902,-1140 4902,-937.17
  text "COMPONENTS MARKED 'DNP' SHOULD NOT BE POPULATED." at 1153.5,-318.5 h60
  text "ASSEMBLY VARIANT:" at 1153,-434 h60
  text ".VariantName" at 2189,-434 h60
  text "PCB VIEWED FROM TOP SIDE" at -228.5,-655.67 h60
  text "BOARD #:" at 2248,-655.67 h60
  text ".PRJ_Number" at 2793.5,-655.67 h60
  text "REV:" at 3638,-655.67 h60
  text ".PCB_Rev" at 3929.5,-655.67 h60
  text "SVN REV:" at 4476,-655.67 h60
  text ".VersionControl_RevNumber" at 4982,-655.67 h60
  text "PLOT NAME =" at -228.5,-1064.34 h60
  text ".plot_File_Name" at 577,-1064.34 h60
  text "GENERATED    :" at 2250,-1064.34 h60
  text ".Print_Date" at 3119.5,-1064.34 h60
  text ".Print_Time" at 3848.5,-1064.34 h60
  text "TEXAS INSTRUMENTS" at 5113,-1064.34 h60
M6 Assembly Bottom:
  lines w10: -292.5,-727.33 6309.5,-727.33 ; -290.5,-930.67 6309.5,-930.67 ; 1115.5,-1140.5 1115.5,-937.67 ; 1737.5,-727.33 1737.5,-524 ; 2577.5,-727.33 2577.5,-524 ; 3844.5,-1134 3844.5,-524 ; 4733.5,-1134 6309,-1134 6309,-524 -292.5,-524 -292.5,-1134 2304.5,-1134 6309.5,-1134 6309.5,-524
  text "COMPONENTS MARKED 'DNP' SHOULD NOT BE POPULATED." at 6102,-318 h60
  text ".VariantName" at 5058,-434 h60
  text "ASSEMBLY VARIANT:" at 6097,-434 h60
  text ".VersionControl_RevNumber" at 1035.5,-656.17 h60
  text "SVN REV:" at 1541.5,-656.17 h60
  text ".PCB_Rev" at 2088,-656.17 h60
  text "REV:" at 2379.5,-656.17 h60
  text ".PRJ_Number" at 3224,-656.17 h60
  text "BOARD #:" at 3769.5,-656.17 h60
  text "PCB VIEWED FROM BOTTOM SIDE" at 6246,-656.17 h60
  text "TEXAS INSTRUMENTS" at 904.5,-1064.84 h60
  text ".Print_Time" at 2169,-1064.84 h60
  text ".Print_Date" at 2898,-1064.84 h60
  text "GENERATED    :" at 3767.5,-1064.84 h60
  text ".plot_File_Name" at 5440.5,-1064.84 h60
  text "PLOT NAME =" at 6246,-1064.84 h60
M9 Title Sheet:
  drawing of 57 lines, arcs and shapes, not listed
  text "1" at 739.84,8036.5 h70
  text "2" at 3235.5,8036.5 h70
  text "3" at 5724.84,8036.5 h70
  text "4" at 8231.51,8036.5 h70
  text "5" at 10730.5,8036.5 h70
  text "6" at 13235.5,8036.5 h70
  text "A" at -416.5,6893.5 h70
  text "A" at 14383.5,6893.5 h70
  text "B" at -416.5,4513.5 h70
  text "B" at 14383.5,4513.5 h70
  text "C" at -416.5,2138.5 h70
  text "C" at 14383.5,2138.5 h70
  text "PROJECT TITLE:" at 11343.5,277.5 h45
  text ".PRJ_Title" at 11393.5,144.17 h70
  text "DESIGNED FOR:" at 11343.5,-23.5 h45
  text ".PRJ_Customer" at 11393.5,-163.5 h70
  text "D" at -416.5,-231.5 h70
  text "D" at 14383.5,-231.5 h70
  text "FILE NAME:" at 11343.5,-323.5 h45
  text ".PCB_File_Name_No_Path" at 11393.5,-443.5 h70
  text "Texas Instruments (TI) and/or its licensors do not warrant the accuracy or completeness of this specification" at 6374,-605.34 h45
  text "ENGINEER:" at 11343.5,-613.5 h45
  text "LAYOUT BY:" at 12848.5,-613.5 h45
  text "or any information contained therein. TI and/or its licensors do not warrant that this design will meet" at 6329.01,-718 h45
  text ".PRJ_Engineer" at 11393.5,-768.49 h70
  text ".PCB_Layout" at 12899,-768.49 h70
  text "the specifications, will be suitable for your application or fit for any particular purpose, or will operate in" at 6329.01,-830.67 h45
  text ".Layer_Name" at 577,-858.49 h60
  text "ALTIUM DESIGNER VERSION:" at 12848.5,-923.5 h45
  text "an implementation. TI and/or its licensors do not warrant that the design is production worthy. You should" at 6329.01,-943.33 h45
  text "completely validate and test your design implementation to confirm the system functionality for your application." at 6374,-1056 h45
  text ".print_Scale" at 11393.5,-1056.83 h70
  text ".Application_BuildNumber" at 12899,-1056.83 h70
  text "1" at 739.84,-1263.5 h70
  text "2" at 3235.5,-1263.5 h70
  text "3" at 5724.84,-1263.5 h70
  text "4" at 8231.51,-1263.5 h70
  text "5" at 10730.5,-1263.5 h70
  text "6" at 13235.5,-1263.5 h70
M10 Fab Notes:
  drawing of 185 lines, arcs and shapes, not listed
  text "DESIGN INFORMATION" at 12381.02,5910 h60
  text "MIN. TRACK WIDTH:" at 11736.46,5730 h60
  text "8" at 12832.7,5730 h60
  text "MIL" at 12987.46,5730 h60
  text "MIN. CLEARANCE:" at 11736.46,5598 h60
  text "0.2" at 12772.7,5598 h60
  text "mm" at 12987.46,5598 h60
  text "MIN. VIA PAD SIZE:" at 11736.46,5466 h60
  text "24" at 12802.71,5466 h60
  text "MIL" at 12987.46,5466 h60
  text "0.05mm (2MIL)" at 12431.46,5324.29 h60
  text "MINIMUM ANNULAR RING" at 11407.23,5320 h60
  text "EXTERNAL" at 13139.46,5320 h60
  text "PER" at 11607.23,5202 h60
  text "IPC-D-275 CLASS 2 LEVEL C" at 11827.23,5202 h60
  text "MIL, HOLES" at 13315.46,5089.71 h60
  text "+/-" at 12923,5089 h60
  text "+/-" at 13777,5089 h60
  text "REGISTRATION TOLERANCES:" at 11407.23,5084 h60
  text "METAL" at 12607,5084 h60
  text "5" at 13183.2,5084 h60
  text "3" at 14016.2,5084 h60
  text "MIL" at 14132.46,5084 h60
  text "MATERIAL:" at 11332.46,4874.54 h60
  text "FR-4 High Tg" at 12318.9,4734.21 h60
  text "FR-408" at 11753.46,4725.64 h60
  text "X" at 12165.46,4725.64 h60
  text "OTHER" at 13241.46,4725.64 h60
  text "62 MIL (1.6mm) +/-10%" at 12073.56,4562.92 h60
  text "THICKNESS:" at 11407.23,4558.64 h60
  text "X" at 11945.4,4558.64 h60
  text "OTHER" at 13358.46,4558.64 h60
  text "TOLERANCE:" at 11407.23,4400.64 h60
  text "X" at 12246.53,4400.64 h60
  text "ANSI IPC-6012 TYPE 3 CLASS 2" at 12433.48,4400.64 h60
  text "OTHER +/-" at 12433.46,4244.64 h60
  text "BOW & TWIST:" at 11407.23,4087.64 h60
  text "X" at 12246.53,4087.64 h60
  text "ANSI IPC-6012 TYPE 3 CLASS 2" at 12433.48,4087.64 h60
  text "OTHER +/-" at 12433.46,3929.13 h60
  text "DRILLING:" at 11332.46,3790.64 h60
  text "REFERENCE:" at 11407.23,3673.64 h60
  text "X" at 12055.46,3673.64 h60
  text "AS SHOWN" at 12242.46,3673.64 h60
  text "X" at 12956.46,3673.64 h60
  text "NC_DRILL FILES" at 13093.46,3673.64 h60
  text "PTH MIN COPPER THICKNESS:" at 11407.23,3515.64 h60
  text "X" at 12757.46,3515.64 h60
  text "1MIL" at 12894.46,3515.64 h60
  text "OTHER" at 13391.46,3515.64 h60
  text "BOARD FINISH:" at 11332.46,3356.64 h60
  text "SILKSCREEN:" at 11487.68,3238.64 h60
  text "X" at 12436.46,3238.64 h60
  text "TOP" at 12562.46,3238.64 h60
  text "X" at 12946.46,3238.64 h60
  text "BOTTOM" at 13073.46,3238.64 h60
  text "SILKSCREEN COLOR:" at 11487.68,3071.64 h60
  text "X" at 12435.42,3071.64 h60
  text "WHITE" at 12562.46,3071.64 h60
  text "OTHER" at 13073.46,3071.64 h60
  text "SOLDER RESIST COLOR:" at 11487.68,2901.64 h60
  text "GREEN" at 12182.46,2742.44 h60
  text "BLUE" at 12773.46,2742.44 h60
  text "OTHER" at 13311.46,2742.44 h60
  text "X" at 12650,2740 h60
  text "IMMERSION GOLD (ENIG)" at 12393.46,2553.92 h60
  text "ENEPIG" at 13731,2550.64 h60
  text "SURFACE FINISH:" at 11332.46,2549.64 h60
  text "X" at 11520,2395 h60
  text "IMM. TIN/SILVER OR EQUIV" at 11662,2392.64 h60
  text "OTHER" at 13093.46,2392.64 h60
  text "ARRAY/PANEL:" at 11332.46,2213.64 h60
  text "CUT AND TRIM PER MECH LAYER 1" at 12393.46,2209.35 h60
  text "N.C. ROUTE" at 12393.46,2057.64 h60
  text "X" at 13072.46,2057.64 h60
  text "V. SCORE" at 13259.46,2057.64 h60
  text "CERTIFICATION:" at 11332.46,1920.64 h60
  text "MATERIALS AND WORKMANSHIP FOR ALL PCBS" at 12057.46,1920.64 h60
  text "TO MEET OR EXCEED THE REQUIREMENTS OF:" at 12057.46,1822.64 h60
  text "X" at 11683.96,1686.13 h60
  text "ANSI IPC-A-600F CLASS ->" at 11822.96,1686.13 h60
  text "X" at 13462.02,1686.13 h60
  text "2" at 13580.96,1686.14 h60
  text "1" at 13265.96,1684.64 h60
  text "3" at 13934.96,1684.64 h60
  text "X" at 11686.02,1526.64 h60
  text "UL 94V-0" at 11822.96,1526.64 h60
  text "X" at 12498.02,1526.64 h60
  text "RoHS" at 12634.96,1526.64 h60
  text "OTHER" at 13279.36,1526.64 h60
  text "PER ORDER" at 13676.42,1526.64 h60
  text "ADDITIONAL REQUIREMENTS:" at 11332.46,1385.64 h60
  text "MICROSECTION:" at 11407.23,1270.64 h60
  text "YES" at 12312.96,1270.64 h60
  text "REQUIRED" at 13174.46,1114.49 h60
  text "BARE BOARD ELEC. TEST:" at 11407.23,1111.64 h60
  text "NONE" at 12712.96,1111.64 h60
  text "X" at 13047.46,1111.64 h60
  text "PER ORDER" at 13766.46,1111.64 h60
  text "MANUFACTURER'S UL:" at 11407.23,954.64 h60
  text "RAIL" at 12572.96,950.35 h60
  text "METAL" at 13064.77,950.35 h60
  text "X" at 13440,950 h60
  text "SILK" at 13576.46,950.35 h60
  text ".Layer_Name" at 577,-858.49 h60
M11 Gerber Information:
  lines w10: -292,-930.17 6308,-930.17 ; -292,-726.83 6310,-726.83 ; -292,-523.5 -292,-1133.5 3713,-1133.5 6310,-1133.5 6310,-523.5 -291.5,-523.5 -291.5,-1133.5 1284,-1133.5 ; 2173,-1133.5 2173,-523.5 ; 3440,-726.83 3440,-523.5 ; 4280,-726.83 4280,-523.5 ; 4902,-1140 4902,-937.17
  text "ALL ARTWORK VIEWED FROM TOP SIDE" at -228.5,-655.67 h60
  text "BOARD #:" at 2248,-655.67 h60
  text ".PRJ_Number" at 2793.5,-655.67 h60
  text "REV:" at 3638,-655.67 h60
  text ".PCB_Rev" at 3929.5,-655.67 h60
  text "SVN REV:" at 4476,-655.67 h60
  text ".VersionControl_RevNumber" at 4982,-655.67 h60
  text "LAYER NAME =" at -228.5,-858.49 h60
  text "PLOT NAME =" at -228.5,-1064.34 h60
  text ".plot_File_Name" at 577,-1064.34 h60
  text "GENERATED    :" at 2250,-1064.34 h60
  text ".Print_Date" at 3119.5,-1064.34 h60
  text ".Print_Time" at 3848.5,-1064.34 h60
  text "TEXAS INSTRUMENTS" at 5113,-1064.34 h60
M12 Stackup:
  drawing of 295 lines, arcs and shapes, not listed
  text "Layer" at 9790.35,7845 h60
  text "Name" at 10200.26,7845 h60
  text "Material" at 11140,7845 h60
  text "Thickness" at 11999.77,7845 h60
  text "Constant" at 12649.6,7845 h60
  text "Board Layer Stack" at 13219.46,7845 h60
  text "1" at 9790.35,7725 h60
  text "Top Overlay" at 10200.26,7725 h60
  text "2" at 9790.35,7605 h60
  text "Top Solder" at 10200.26,7605 h60
  text "Solder Resist" at 11140,7605 h60
  text "0.40mil" at 11999.77,7605 h60
  text "3.5" at 12649.6,7605 h60
  text "3" at 9790.35,7485 h60
  text "Top Layer" at 10200.26,7485 h60
  text "Copper" at 11140,7485 h60
  text "1.40mil" at 11999.77,7485 h60
  text "4" at 9790.35,7365 h60
  text "Dielectric1" at 10200.26,7365 h60
  text "FR-4" at 11140,7365 h60
  text "59.20mil" at 11999.77,7365 h60
  text "4.8" at 12649.6,7365 h60
  text "5" at 9790.35,7245 h60
  text "Signal Layer 1" at 10200.26,7245 h60
  text "Copper" at 11140,7245 h60
  text "1.42mil" at 11999.77,7245 h60
  text "6" at 9790.35,7125 h60
  text "Dielectric 3" at 10200.26,7125 h60
  text "5.00mil" at 11999.77,7125 h60
  text "4.2" at 12649.6,7125 h60
  text "7" at 9790.35,7005 h60
  text "Signal Layer 2" at 10200.26,7005 h60
  text "Copper" at 11140,7005 h60
  text "1.42mil" at 11999.77,7005 h60
  text "8" at 9790.35,6885 h60
  text "Dielectric 2" at 10200.26,6885 h60
  text "10.00mil" at 11999.77,6885 h60
  text "4.2" at 12649.6,6885 h60
  text "9" at 9790.35,6765 h60
  text "Bottom Layer" at 10200.26,6765 h60
  text "Copper" at 11140,6765 h60
  text "1.40mil" at 11999.77,6765 h60
  text "10" at 9790.35,6645 h60
  text "Bottom Solder" at 10200.26,6645 h60
  text "Solder Resist" at 11140,6645 h60
  text "0.40mil" at 11999.77,6645 h60
  text "3.5" at 12649.6,6645 h60
  text "11" at 9790.35,6525 h60
  text "Bottom Overlay" at 10200.26,6525 h60
  text ".Layer_Name" at 577,-858.49 h60
M13 Component Bodies Top:
  text ".Layer_Name" at 577,-858.49 h60
M14 Component Bodies Bottom:
  text ".Layer_Name" at 577,-858.49 h60
M15 Courtyards Top:
  text ".Layer_Name" at 577,-858.49 h60
M16 Courtyards Bottom:
  text ".Layer_Name" at 577,-858.49 h60
Drill Drawing:
  circle w1: c34912.72,13581.04 r24.89
  lines w1: 34887.83,12672.68 34900.27,12672.68 34900.27,12660.24 34925.16,12660.24 34925.16,12672.68 34937.6,12672.68 34937.6,12697.57 34925.16,12697.57 34925.16,12710.01 34900.27,12710.01 34900.27,12697.57 34887.83,12697.57 34887.83,12672.68 ; 34887.83,12859.33 34937.6,12859.33 34912.72,12809.56 34887.83,12859.33 ; 34887.83,12971.32 34900.27,12971.32 34912.72,12958.88 34925.16,12971.32 34937.6,12971.32 34925.16,12983.76 34937.6,12996.21 34925.16,12996.21 34912.72,13008.65 34900.27,12996.21 34887.83,12996.21 34900.27,12983.76 34887.83,12971.32 ; 34887.83,13108.2 34912.72,13120.64 34937.6,13108.2 34925.16,13133.08 34937.6,13157.97 34912.72,13145.53 34887.83,13157.97 34900.27,13133.08 34887.83,13108.2 ; 34887.83,13282.4 34912.72,13257.52 34937.6,13282.4 34912.72,13307.29 34887.83,13282.4 ; 34887.83,13406.84 34887.83,13419.28 34900.27,13431.72 34887.83,13444.17 34887.83,13456.61 34900.27,13456.61 34912.72,13444.17 34925.16,13456.61 34937.6,13456.61 34937.6,13444.17 34925.16,13431.72 34937.6,13419.28 34937.6,13406.84 34925.16,13406.84 34912.72,13419.28 34900.27,13406.84 34887.83,13406.84
  lines w12: 34820,12615.44 36938.02,12615.44 ; 34820,13660.68 36938.02,13660.68 ; 35190.36,12466.12 35190.36,13810 ; 35547.36,12466.12 35547.36,13810 ; 36208.93,12466.12 36208.93,13810 ; 36493.07,12466.12 36493.07,13810 ; 34820,12466.12 36938.02,12466.12 36938.02,13810 34820,13810 34820,12466.12
  text "Symbol" at 34909.59,13705.48 h72
  text "Quantity" at 35235.16,13705.48 h72
  text "Finished Hole Size" at 35592.16,13705.48 h72
  text "Plated" at 36253.72,13705.48 h72
  text "Hole Type" at 36537.86,13705.48 h72
  text "20" at 35235.16,13556.16 h60
  text "7.87mil (0.200mm)" at 35592.16,13556.16 h60
  text "PTH" at 36253.72,13556.16 h60
  text "Round" at 36537.86,13556.16 h60
  text "5" at 35235.16,13406.84 h60
  text "8.00mil (0.203mm)" at 35592.16,13406.84 h60
  text "PTH" at 36253.72,13406.84 h60
  text "Round" at 36537.86,13406.84 h60
  text "193" at 35235.16,13257.52 h60
  text "16.00mil (0.406mm)" at 35592.16,13257.52 h60
  text "PTH" at 36253.72,13257.52 h60
  text "Round" at 36537.86,13257.52 h60
  text "16" at 35235.16,13108.2 h60
  text "37.40mil (0.950mm)" at 35592.16,13108.2 h60
  text "PTH" at 36253.72,13108.2 h60
  text "Round" at 36537.86,13108.2 h60
  text "92" at 35235.16,12958.88 h60
  text "40.00mil (1.016mm)" at 35592.16,12958.88 h60
  text "PTH" at 36253.72,12958.88 h60
  text "Round" at 36537.86,12958.88 h60
  text "18" at 35235.16,12809.56 h60
  text "50.00mil (1.270mm)" at 35592.16,12809.56 h60
  text "PTH" at 36253.72,12809.56 h60
  text "Round" at 36537.86,12809.56 h60
  text "8" at 35235.16,12660.24 h60
  text "90.55mil (2.300mm)" at 35592.16,12660.24 h60
  text "PTH" at 36253.72,12660.24 h60
  text "Round" at 36537.86,12660.24 h60
  text "352 Total" at 35235.16,12510.92 h60
  text ".Layer_Name" at 577,-858.49 h60

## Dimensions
0,0 to 4320,0 on M2 Board Dimensions
0,0 to 0,3450 on M2 Board Dimensions
0,-400 to 1000,-400 on M2 Board Dimensions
